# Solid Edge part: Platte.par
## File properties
Dokumentum tartalom típus: 0
Last saved by: bmolnar
Revision: 77
Sűrűség: 0,000 kg/m^3
Pontosság: 0,990
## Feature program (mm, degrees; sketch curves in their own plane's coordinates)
base feature "unnamed BaseFeature 1"
thread "unnamed Thread 1"
thread "unnamed Thread 2"
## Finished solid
Body 1: solid body, 65 faces, 114 edges, 88 vertices.
  Faces by surface: plane 38, cylinder 12, cone 10, torus 5
  Edges by curve: line 60, circle 36, spline 18
Bounding box of the edges (mm; curved faces can reach further): 105.000 x 30.000 x 12.000, from (-52.5, -15, -6) to (52.5, 15, 6).
Cylindrical faces by radius (mm): R2.4585 x2, R2.5 x2, R2.9 x2, R4.25 x2, R5 x2, R6.5 x1, R11 x1
Conical faces (half-angle, radius in mm at the cone's reference point): 45 deg R2.9585 x4, 45 deg R3 x2, 45 deg R11.25 x1, 60 deg R1 x2, 60 deg R1.4434 x1
Toroidal faces (ring radius, tube radius in mm): R2.6 r0.1 x2, R3.75 r0.5 x2, R5.7 r0.8 x1
Planar faces by outward normal: +x 1, +y 4, +z 7, -x 1, -y 4, -z 5, oblique 16
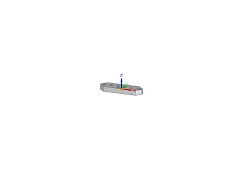
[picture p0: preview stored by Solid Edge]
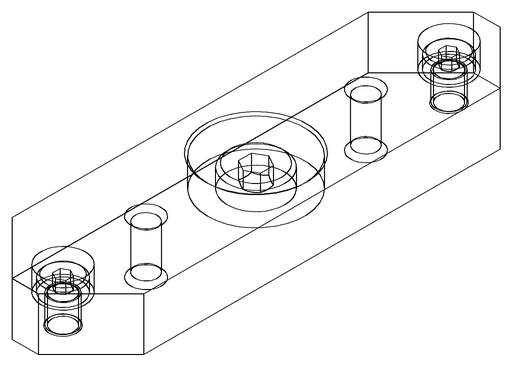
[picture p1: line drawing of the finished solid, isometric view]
